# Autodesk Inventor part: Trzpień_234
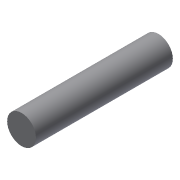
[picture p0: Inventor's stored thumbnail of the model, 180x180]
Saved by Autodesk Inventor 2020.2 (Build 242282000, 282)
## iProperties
Created: 2014-01
Part Number: Trzpień_234
Material: Ogólny
Document SubType Name: Modeling
Designer: F.Stasiak
Density: 1 g/cm^3
Appearance: Domyślna
Manager: www.cadconsulting.pl
Company: Fabian Stasiak CAD Consulting
Author: F.Stasiak
Subject: Zbiór ćwiczeń. Autodesk Inventor 2020. Kurs podstawowy
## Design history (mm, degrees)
sketch "Szkic1"
  geometry: C1 r 1 at (0, 0); 1 further point
  constraints: 1 centre point, 1 coincident
  dimensions: "d0" = 2 diameter of C1
extrude "Wyciągnięcie proste1" new body sketch "Szkic1" stored distance "d1" = 9.5; taper "d2" = 0 deg
node "Bryła1"
